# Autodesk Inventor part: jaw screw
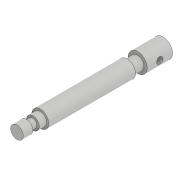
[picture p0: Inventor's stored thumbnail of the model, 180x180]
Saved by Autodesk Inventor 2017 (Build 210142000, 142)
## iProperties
Created: 2016-03
Part Number: jaw screw
Material: Generic
Document SubType Name: Modeling
Designer: Sandeep
Density: 1 g/cm^3
Appearance: Default
Author: Sandeep
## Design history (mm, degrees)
sketch "Sketch1"
  geometry: L1 (0, -138)-(-6, -138); L2 (-6, -116)-(-6, -116); L3 (-6, -116)-(-8, -116); L4 (-8, -116)-(-8, -34); L5 (-8, -34)-(-6, -34); L6 (-6, -34)-(-6, -24); L7 (-6, -24)-(-9, -24); L8 (-9, -24)-(-9, 0); L9 (-9, 0)-(0, 0); L10 (0, 0)-(0, -138); L11 (0, 0)-(0, 14.581); L12 (-6, -116)-(-6, -123); L13 (-6, -123)-(-4, -123); L14 (-4, -123)-(-4, -129); L15 (-4, -129)-(-6, -129); L16 (-6, -129)-(-6, -138); 1 other entity
  constraints: 32 end point, 10 perpendicular, 3 point on line, 3 vertical, 1 coincident, 1 horizontal, 2 other
  dimensions: "d0" = 18 diameter of L8 L11; "d1" = 12 diameter of L6 L11; "d3" = 24 distance of L7.end L8.end; "d4" = 10 distance of L5.end L6.end; "d5" = 82 distance of L3.end L4.end; "d6" = 138 distance between parallel lines of L1 L9; "d8" = 16 diameter of L4 L11; "d10" = 6 distance of L13.end L14.end; "d11" = 9 distance of L15.end L1.end; "d12" = 8 diameter of L14 L11
revolve "Revolution1" sketch "Sketch1" stored, may be unused: angle "d9" = 90 deg
sketch "Sketch2"
  geometry: L1 (0, -9)-(0, 9) reference; L2 (0, 0)-(-20.975, 0); C1 r 3 at (-12, 0)
  constraints: 2 end point, 1 centre point, 1 horizontal, 1 point on line
  dimensions: "d13" = 6 diameter of C1; "d14" = 12 distance from line of L1 C1.centre
extrude "Extrusion1" cut sketch "Sketch2" distance "d15" = 25; taper "d16" = 0 deg
body "Solid1"
